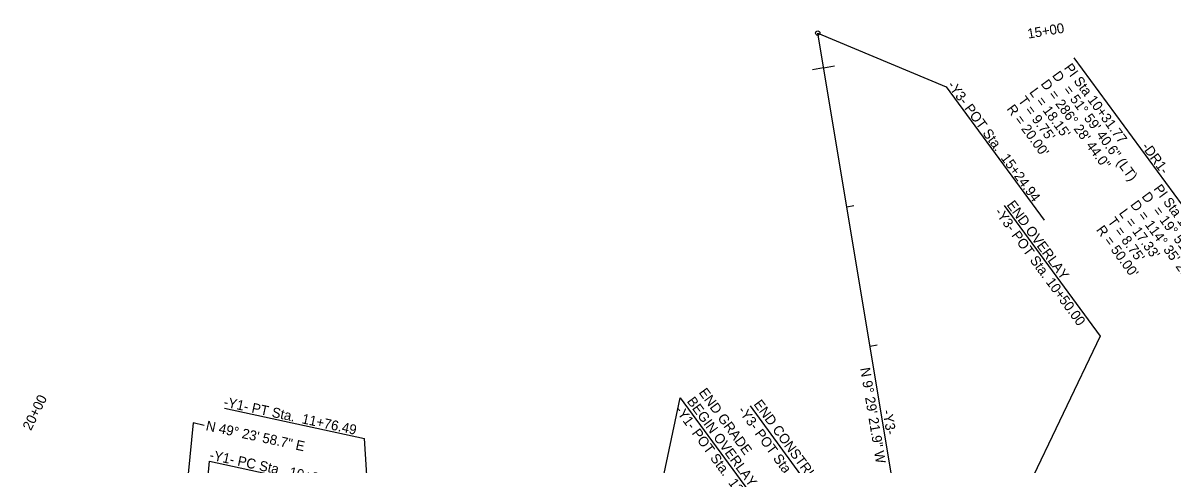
# Model space of a CAD drawing. Extents: x 1762196 to 1766326, y 709922 to 713142.
# Drawn here: x 1763221 to 1764036, y 712620 to 712933 of the extents above; entities that cross this region are included whole.
import ezdxf

# ---------------------------------------------------------------- set-up
doc = ezdxf.new("R2010")
doc.units = 0
for name, color, linetype in [('Prop Horizontal Alignment', 7, 'Continuous'), ('Prop Horizontal Alignment Curve and Spiral Data', 7, 'Continuous'), ('Prop Horizontal Alignment Direction Label', 7, 'Continuous'), ('Prop Horizontal Alignment Station Label', 7, 'Continuous'), ('Prop Horizontal Alignment Tick Label', 7, 'Continuous'), ('Prop Horizontal Alignment Tick Large', 7, 'Continuous'), ('Prop Horizontal Alignment Tick Small', 7, 'Continuous')]:
    doc.layers.add(name, color=color, linetype=linetype)

msp = doc.modelspace()

# ---------------------------------------------------------------- linework, layer by layer
at = {"layer": 'Prop Horizontal Alignment'}
msp.add_line((1763870.46, 712408.3), (1763783.92, 712926.06), dxfattribs=at)
at = {"layer": 'Prop Horizontal Alignment Curve and Spiral Data'}
msp.add_line((1763965.48, 712908.59), (1764086.47, 712743.96), dxfattribs=at)
at = {"layer": 'Prop Horizontal Alignment Station Label'}
for p, q in [((1763783.92, 712926.06), (1763874.95, 712888.03)), ((1763874.95, 712888.03), (1763944.41, 712793.52)), ((1763916.08, 712803.96), (1763984.12, 712711.37)), ((1763984.12, 712711.37), (1763862.22, 712457.62)), ((1763641.6, 712457.38), (1763686.48, 712667.75)), ((1763686.48, 712667.75), (1763757.27, 712571.42)), ((1763363.33, 712660.39), (1763462.61, 712639.04)), ((1763735.91, 712662.18), (1763802.81, 712571.14)), ((1763341.29, 712649.99), (1763320.6, 712443.44)), ((1763349.05, 712648.32), (1763341.29, 712649.99)), ((1763471.86, 712493.33), (1763462.61, 712639.04)), ((1763339.51, 712459.65), (1763352.65, 712622.89)), ((1763352.65, 712622.89), (1763456.54, 712600.55))]:
    msp.add_line(p, q, dxfattribs=at)
msp.add_circle((1763783.92, 712926.06), 1.5, dxfattribs=at)
at = {"layer": 'Prop Horizontal Alignment Tick Large'}
for q in [(1763780.14, 712900.14), (1763795.92, 712902.78)]:
    msp.add_line((1763788.03, 712901.46), q, dxfattribs=at)
at = {"layer": 'Prop Horizontal Alignment Tick Small'}
for p, q in [((1763809.45, 712803.66), (1763804.52, 712802.83)), ((1763825.94, 712705.02), (1763821, 712704.2))]:
    msp.add_line(p, q, dxfattribs=at)

# ---------------------------------------------------------------- texts
at = {"layer": 'Prop Horizontal Alignment Curve and Spiral Data'}
for s, rotation, p in [('PI Sta 10+31.77', 306.313, (1763958.22, 712901.38)), ('D', 306.313, (1763949.76, 712896)), ("L = 18.15'", 306.313, (1763933.64, 712884.16)), ('D = 286%%d 28\' 44.0"', 306.313, (1763941.7, 712890.08)), ('= 51%%d 59\' 40.6" (LT)', 306.313, (1763957.61, 712885.82)), ("T = 9.75'", 306.313, (1763925.59, 712878.24)), ("R = 20.00'", 306.313, (1763917.53, 712872.31)), ('-DR1-', 306.31306, (1764013.16, 712845.61)), ('D', 306.313, (1764013.24, 712810.38)), ('PI Sta 10+71.79', 306.313, (1764021.69, 712815.76)), ('D = 114%%d 35\' 29.6"', 306.313, (1764005.18, 712804.46)), ("L = 17.33'", 306.313, (1763997.12, 712798.53)), ('= 19%%d 51\' 43.8" (RT)', 306.313, (1764021.08, 712800.2)), ("R = 50.00'", 306.313, (1763981.01, 712786.69)), ("T = 8.75'", 306.313, (1763989.06, 712792.61))]:
    msp.add_text(s, height=7, rotation=rotation, dxfattribs=at).set_placement(p)
at = {"layer": 'Prop Horizontal Alignment Direction Label'}
for s, rotation, p in [('N 9%%d 29\' 21.9" W', 279.48942, (1763813.99, 712688.7)), ('-Y3-', 279.59655, (1763829.82, 712658.66)), ('N 49%%d 23\' 58.7" E', 347.86385, (1763349.74, 712644.9))]:
    msp.add_text(s, height=7, rotation=rotation, dxfattribs=at).set_placement(p)
at = {"layer": 'Prop Horizontal Alignment Station Label'}
for s, rotation, p in [('-Y3- POT Sta.  15+24.94', 306.31306, (1763875.47, 712889.1)), ('END OVERLAY', 306.31306, (1763917.57, 712804.37)), ('-Y3- POT Sta. 10+50.00', 306.31306, (1763908.94, 712799.22)), ('END GRADE', 306.31306, (1763699.29, 712671.54)), ('-Y1- PT Sta.  11+76.49', 347.86385, (1763362.34, 712661.75)), ('BEGIN OVERLAY', 306.31306, (1763690.83, 712665.33)), ('END CONSTRUCTION', 306.31306, (1763738.17, 712663.28)), ('-Y1- POT Sta.  13+50.00', 306.31306, (1763682.36, 712659.11)), ('-Y3- POT Sta. 10+75.00', 306.31306, (1763726.95, 712658.82)), ('-Y1- PC Sta.  10+35.00', 347.86385, (1763352.33, 712624.19))]:
    msp.add_text(s, height=7, rotation=rotation, dxfattribs=at).set_placement(p)
at = {"layer": 'Prop Horizontal Alignment Tick Label'}
for s, rotation, p in [('15+00', 9.48942, (1763933.15, 712922.1)), ('20+00', 63.59667, (1763226.15, 712644.14))]:
    msp.add_text(s, height=7, rotation=rotation, dxfattribs=at).set_placement(p)

doc.saveas('drawing.dxf')
